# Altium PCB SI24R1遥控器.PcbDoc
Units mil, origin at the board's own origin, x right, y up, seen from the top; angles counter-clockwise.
Board outline 3937 x 3344.8 mil, 2 copper layers (Top Layer, Bottom Layer); 46 components, 39 nets, 207 pads, 28 vias.
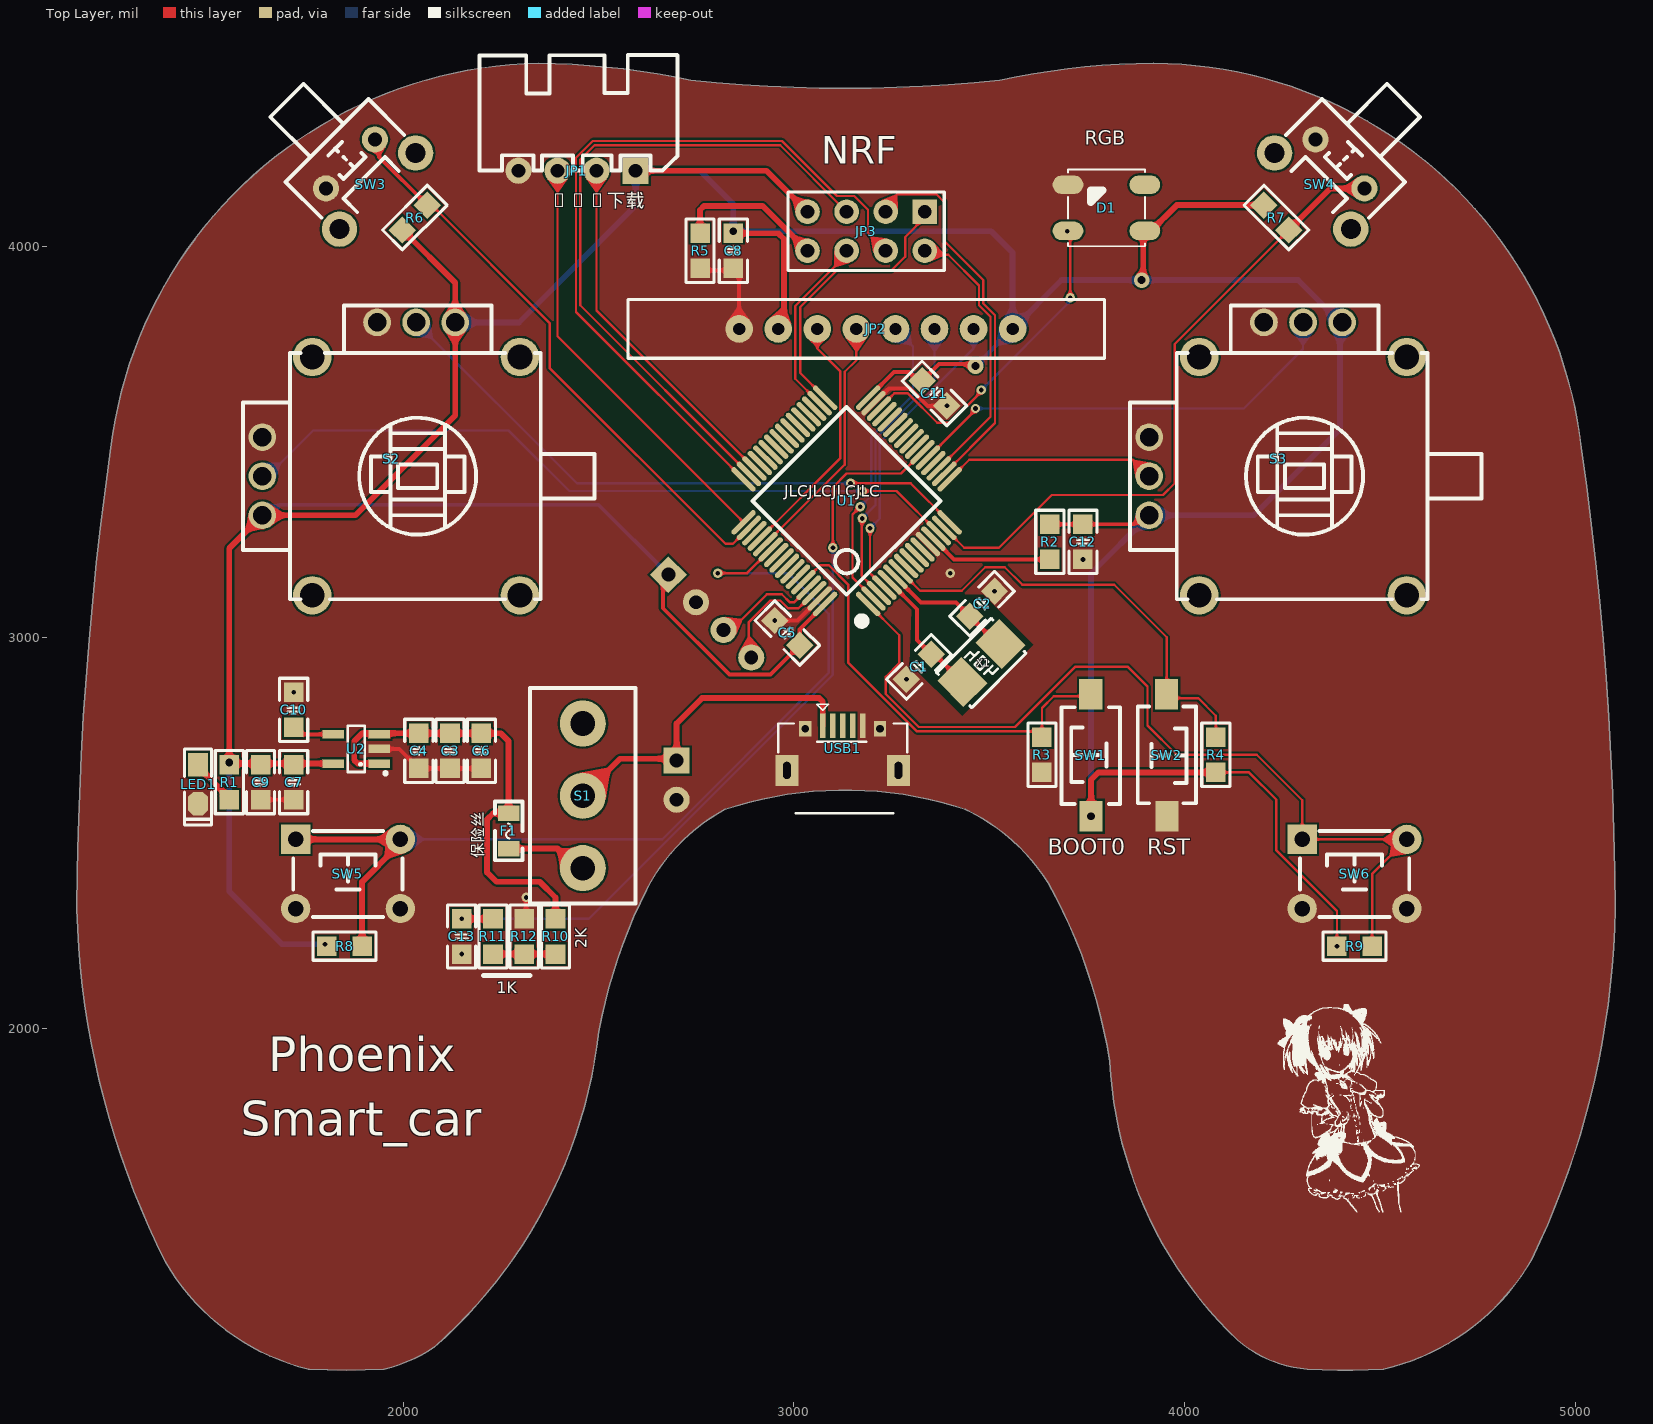
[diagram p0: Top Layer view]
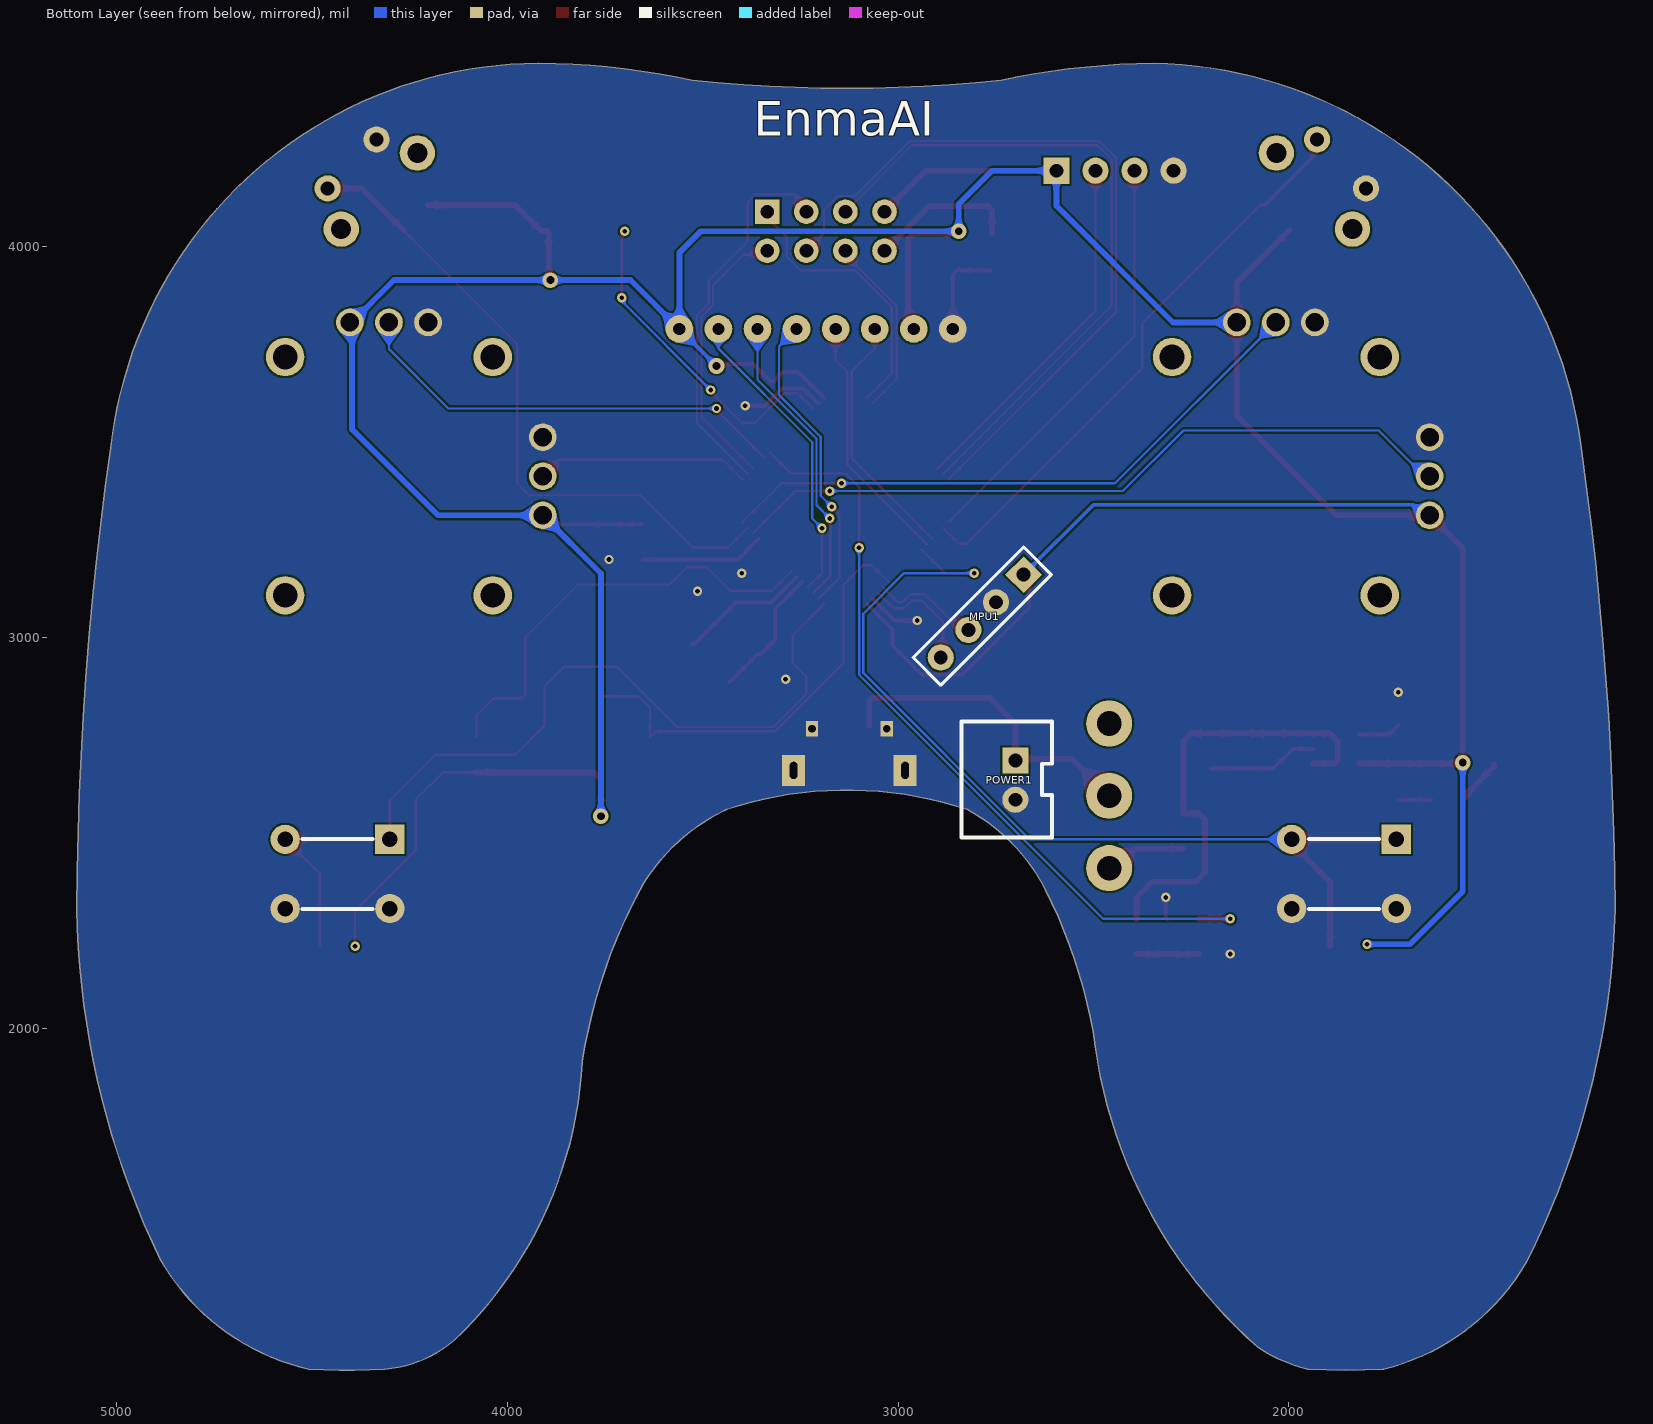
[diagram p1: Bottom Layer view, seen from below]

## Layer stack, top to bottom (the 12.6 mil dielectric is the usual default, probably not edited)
Top Solder: solder mask 0.4, Solder Resist, Dk 3.5
Top Layer: signal copper 1.4
Dielectric 1: dielectric 12.6, FR-4, Dk 4.8
Bottom Layer: signal copper 1.4
Bottom Solder: solder mask 0.4, Solder Resist, Dk 3.5

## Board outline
1391.35,1403.01 ccw(c1896.05,1692.9) 1758.26,1127.42 ccw(c1854.72,3093.56) 1951.17,1127.42 ccw(c1858.16,1512.49) 2080.33,1184.51 ccw(c1244.42,2133.09) 2489.78,1914.82 cw(c3809.86,1754.87) 2623.64,2355.76 cw(c3053.63,2134.86) 2824.42,2560.49 2822.89,2560.01 cw(c3131.51,1625.39) 3440.13,2560.01 3438.6,2560.49 cw(c3223.76,2104.73) 3651.2,2371.51 cw(c2447.28,1700.87) 3808.68,1914.82 ccw(c4866.07,1968.48) 4135.45,1202.22 ccw(c4338.85,1437.13) 4313.68,1127.42 ccw(c4411.21,3093.5) 4508.75,1127.42 ccw(c4376.69,1703.01) 4888.5,1408.39 ccw(c2976.27,2337.47) 5102,2304.49 5101.99,2304.49 ccw(c-3410.85,2274.06) 5015.39,3485.6 ccw(c3915.01,3362.63) 3920.9,4469.85 ccw(c3935.61,2507.77) 3527.2,4426.93 cw(c3130.23,8185.49) 2736.09,4426.63 ccw(c2324.92,2497.47) 2346.1,4469.85 ccw(c2365.85,3347.23) 1251.61,3485.59 1251.61,3485.6 ccw(c9946.59,2254.27) 1165,2304.5 1165,2304.49 ccw(c3290.29,2358.97)

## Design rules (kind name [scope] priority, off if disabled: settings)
Clearance [All] p1: gap=5 ignorepadtopadclearanceinfootprint=FALSE
Height [All] p1: minheight=0 maxheight=10000 prefheight=500
HoleSize [All] p1: absolutevalues=TRUE maxlimit=1000 minlimit=1 maxpercent=80.000 minpercent=20.000
HoleToHoleClearance [All] p1: gap=0 allowstackedmicrovias=TRUE
MinimumSolderMaskSliver [All] p1: minsoldermaskwidth=0
PlaneConnect [All] p1: planeconnectstyle=Direct reliefexpansion=20 reliefentries=4 reliefconductorwidth=10 reliefairgap=10
PolygonConnect [All] p1: connectstyle=Direct reliefconductorwidth=10 reliefentries=4 polygonreliefangle="90 Angle" airgapwidth=10
RoutingVias [All] p1: holewidth=12 width=24 viastyle="Through Hole" minholewidth=12 minwidth=24 maxholewidth=50 maxwidth=100
SilkToSilkClearance [All] p1: silktosilkclearance=0
SolderMaskExpansion [All] p1: expansion=4
Width [All] p1: maxlimit=100 minlimit=6 preferedwidth=6
24 further rules are at their usual default settings.

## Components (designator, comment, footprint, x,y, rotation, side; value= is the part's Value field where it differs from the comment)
C1 "18pF" "C 0805_M" 3320,2925 r45 top
C2 "18pF" "C 0805_M" 3481.82,3086.82 r225 top
C3 "100uF" "C 0805_M" 2120,2710 r90 top
C4 "100uF" "C 0805_M" 2040,2710 r90 top
C5 "0.1uF" "C 0805_M" 2983.18,3011.82 r315 top
C6 "22uF" "C 0805_M" 2200,2710 r90 top
C7 "22uF" "C 0805_M" 1720,2630 r90 top
C8 "10uF" "C 0805_M" 2845,3990 r90 top
C9 "10uF" "C 0805_M" 1635,2630 r90 top
C10 "0.1uF" "C 0805_M" 1720,2815 r270 top
C11 "0.1uF" "C 0805_M" 3360,3625 r135 top
C12 "0.1uF" "C 0805_M" 3740,3245 r90 top
C13 "0.1uF" "C 0805_M" 2150,2235 r90 top
D1 "P923D" RGB_LED_5050 3800,4100 r270 top
F1 "1A" "FU 0805" 2270,2505 r90 top
JP1 "HDR-1X4" XH2.54-WI-4P 2445,4195 r180 top
JP2 "HDR-1X8" IPS 2960,3785 r0 top
JP3 "Header 4X2" HDR2.54-LI-2x4P 3185,4040 r180 top
LED1 "蓝色" "LED 0805B" 1475,2625 r270 top
MPU1 "HDR-1X4" HDR2.54-LI-4P 2785,3055 r315 bottom
POWER1 "" XH2.54-LI-2P 2700,2635 r270 bottom
R1 "Res2" "R 0805_M" 1555,2630 r90 top
R2 "0" "R 0805_M" 3655,3245 r90 top
R3 "10K" "R 0805_M" 3635,2700 r270 top
R4 "10K" "R 0805_M" 4080,2700 r90 top
R5 "0" "R 0805_M" 2760,3990 r90 top
R6 "10K" "R 0805_M" 2030,4075 r45 top
R7 "10K" "R 0805_M" 4235,4075 r315 top
R8 "10K" "R 0805_M" 1850,2210 r0 top
R9 "10K" "R 0805_M" 4435,2210 r0 top
R10 "Res2" "R 0805_M" 2390,2235 r90 top
R11 "Res2" "R 0805_M" 2230,2235 r270 top
R12 "Res2" "R 0805_M" 2310,2235 r270 top
S1 "SS-12F23" SS-12D10 2460,2595.04 r90 top
S2 "摇杆" 3D161摇杆 2045,3440 r180 top
S3 "摇杆" 3D161摇杆 4315,3440 r180 top
SW1 "3x6x5" "TSW SMD-3*6*2.5" 3760,2700 r90 top
SW2 "3x6x5" "TSW SMD-3*6*2.5" 3955,2697.69 r270 top
SW3 "6x6x5" "TSW DIP-6*6*7_V" 1865,4212.37 r225 top
SW4 "6x6x5" "TSW DIP-6*6*7_V" 4397.64,4212.36 r135 top
SW5 "6x6x5" "TSW DIP-6*6*6" 1858.86,2395 r0 top
SW6 "6x6x5" "TSW DIP-6*6*6" 4435,2395 r0 top
U1 "MM32SPIN27PS" "LQFP64 10x10_M" 3135,3350 r45 top
U2 "MIC5219" SOT23-5M 1880,2715 r90 top
USB1 "USB-5P" USB-MICRO_A 3125,2660 r0 top
X1 "8MHz" "OSC 5032-2P" 3480,2935 r45 top

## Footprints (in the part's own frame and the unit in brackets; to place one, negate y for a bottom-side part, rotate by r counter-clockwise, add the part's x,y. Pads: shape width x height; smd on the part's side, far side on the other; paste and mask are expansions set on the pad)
3D161摇杆 [mm]
  round 1.8 hole 1.2: 1(10.298,3.226) 2(10.298,0.686) 3(10.298,-1.854) 4(2.838,-9.314) 5(0.298,-9.314) 6(-2.242,-9.314)
  round 2.5 hole 1.6 unplated: ""(-6.453,8.436) ""(-6.453,-7.063) ""(7.048,8.436) ""(7.048,-7.063)
  silkscreen extent -11.3,-10.41 11.56,8.69
"C 0805_M" [mil] "无极性贴片电容                                         淘宝ID:黄晶宝石"
  rect 50x50 smd: 1(-45,0) 2(45,0)
  silkscreen extent -81,-36 81,36, body extent -39,-24 39,24, height 20
"FU 0805" [mil] "贴片保险丝"
  rect 40x55 smd: 1(-45,0) 2(45,0)
  silkscreen extent -75,-35 75,35, body extent -39,-24 39,24, height 20
HDR2.54-LI-2x4P [mm] "双排排针，4x2脚 淘宝ID:黄晶宝石   店铺网址:https://shop463601444.taobao.com"
  rect 1.6x1.6 hole 0.9: 1(-3.81,-1.27)
  round 1.6 hole 0.9: 2(-3.81,1.27) 3(-1.27,-1.27) 4(-1.27,1.27) 5(1.27,-1.27) 6(1.27,1.27) 7(3.81,-1.27) 8(3.81,1.27)
  silkscreen extent -5.08,-2.54 5.08,2.54, body extent -5.08,-2.54 5.08,2.54, height 8.5
HDR2.54-LI-4P [mm] "排针，4脚"
  rect 1.7x1.7 hole 0.9: 1(-3.81,0)
  round 1.7 hole 0.9: 2(-1.27,0) 3(1.27,0) 4(3.81,0)
  silkscreen extent -5.08,-1.27 5.08,1.27, body extent -5.08,-1.27 5.08,1.27, height 8.5
IPS [mm]
  round 1.8 hole 0.8: 1(-2.54,0.127) 2(0,0.127) 3(2.54,0.127) 4(5.08,0.127) 5(7.62,0.127) 6(10.16,0.127) 7(12.7,0.127) 8(15.24,0.127)
  silkscreen extent -9.78,-1.78 21.21,2.05
"LED 0805B" [mil] "蓝色0805LED                                    淘宝ID:黄晶宝石"
  rect 60x50 smd: 1(-50,0)
  oct 60x50 smd: 2(50,0)
  silkscreen extent -90,-35 105,35, body extent -39,-25 39,25, height 32
"LQFP64 10x10_M" [mm] "64脚，体宽10x10mm，脚距0.5mm         淘宝ID:黄晶宝石"
  oval 0.35x2.1 smd: 1(-3.75,-5.727) 2(-3.25,-5.727) 3(-2.75,-5.727) 4(-2.25,-5.727) 5(-1.75,-5.727) 6(-1.25,-5.727) 7(-0.75,-5.727) 8(-0.25,-5.727) 9(0.25,-5.727) 10(0.75,-5.727) 11(1.25,-5.727) 12(1.75,-5.727) 13(2.25,-5.727) 14(2.75,-5.727) 15(3.25,-5.727) 16(3.75,-5.727) 33(3.75,5.727) 34(3.25,5.727) 35(2.75,5.727) 36(2.25,5.727) 37(1.75,5.727) 38(1.25,5.727) 39(0.75,5.727) 40(0.25,5.727) 41(-0.25,5.727) 42(-0.75,5.727) 43(-1.25,5.727) 44(-1.75,5.727) 45(-2.25,5.727) 46(-2.75,5.727) 47(-3.25,5.727) 48(-3.75,5.727)
  oval 2.1x0.35 smd: 17(5.727,-3.75) 18(5.727,-3.25) 19(5.727,-2.75) 20(5.727,-2.25) 21(5.727,-1.75) 22(5.727,-1.25) 23(5.727,-0.75) 24(5.727,-0.25) 25(5.727,0.25) 26(5.727,0.75) 27(5.727,1.25) 28(5.727,1.75) 29(5.727,2.25) 30(5.727,2.75) 31(5.727,3.25) 32(5.727,3.75) 49(-5.727,3.75) 50(-5.727,3.25) 51(-5.727,2.75) 52(-5.727,2.25) 53(-5.727,1.75) 54(-5.727,1.25) 55(-5.727,0.75) 56(-5.727,0.25) 57(-5.727,-0.25) 58(-5.727,-0.75) 59(-5.727,-1.25) 60(-5.727,-1.75) 61(-5.727,-2.25) 62(-5.727,-2.75) 63(-5.727,-3.25) 64(-5.727,-3.75)
  silkscreen extent -5.08,-6.47 4.32,4.32, body extent -6,-6 6,6, height 1.45
"OSC 5032-2P" [mm] "5mm*3.2mm*0.8mm(长*宽*高)                  淘宝ID:黄晶宝石"
  rect 2.2x2.4 smd: 1(-1.75,0) 2(1.75,0)
  silkscreen extent -2.5,-1.6 2.5,1.6, body extent -2.5,-1.6 2.5,1.6, height 0.86
"R 0805_M" [mil] "1/8W贴片电阻"
  rect 50x50 smd: 1(-45,0) 2(45,0)
  silkscreen extent -81,-36 81,36, body extent -39,-25 39,25, height 20
RGB_LED_5050 [mm]
  oval 1.2x2 smd: 1(-1.5,-2.5) 2(1.5,-2.5) 3(1.5,2.5) 4(-1.5,2.5)
  silkscreen extent -2.5,-2.5 2.5,2.5, body extent -2.5,-2.7 2.5,2.7, height 1.55
SOT23-5M [mm] "3x1.6x1.1mm(长宽高) 封装库来自淘宝卖家 ID：黄晶宝石"
  rect 0.55x1.4 smd: 1(-0.95,-1.5) 2(0,-1.5) 3(0.95,-1.5) 4(0.95,1.5) 5(-0.95,1.5)
  silkscreen extent -1.66,-1.98 1.5,0.56, body extent -1.5,-1.4 1.5,1.4, height 1.15
SS-12D10 [mm] "脚距3mm      淘宝ID:黄晶宝石"
  round 3 hole 1.6: 1(-4.7,0) 2(0,0) 3(4.7,0)
  silkscreen extent -7,-3.43 7,3.43, body extent -7,-3.1 7,3.1, height 9.65
"TSW DIP-6*6*6" [mm] "6*6*6mm"
  rect 1.9x1.9 hole 1: 1(-3.4,2.25)
  round 1.9 hole 1: 2(-3.4,-2.25) 3(3.4,-2.25) 4(3.4,2.25)
  silkscreen extent -3.56,-2.79 3.56,2.79, body extent -4.11,-3 4.11,3, height 5.95
"TSW DIP-6*6*7_V" [mm] "侧按轻触开关 6*6*7mm           淘宝ID:黄晶宝石"
  round 2.3 hole 1.3: 0(-3.5,2.5) 0(3.5,2.5)
  round 1.7 hole 0.9: 1(-2.25,0) 2(2.25,0)
  silkscreen extent -3.81,-5.84 3.81,2.54, body extent -4.18,-5.72 4.18,4.13, height 7.47
"TSW SMD-3*6*2.5" [mm] "3*6*2.5mm"
  rect 2x1.5 smd: 1(-3.996,-0.02) 2(3.937,0)
  silkscreen extent -3.21,-1.9 3.09,1.9, body extent -4,-1.88 4,1.62, height 2.59
USB-MICRO_A [mm] "micro型USB ，5.7*7.8*2.5mm"
  rect 0.35x1.6 smd: 1(-1.3,2.9) 2(-0.65,2.9) 3(0,2.9) 4(0.65,2.9) 5(1.3,2.9)
  rect 1.5x2 hole 0.5 slot 1.1 at 90 deg: 5(-3.625,0) 5(3.625,0)
  rect 0.8x1 hole 0.5: 5(-2.425,2.71) 5(2.425,2.71)
  silkscreen extent -4.19,-2.79 4.19,4.3, body extent -4,-2.71 4,2.89, height 2.8
XH2.54-LI-2P [mm] "接插件，2P  淘宝ID:黄晶宝石   店铺网址:https://shop463601444.taobao.com"
  rect 1.7x1.7 hole 0.9: 1(-1.27,0)
  round 1.7 hole 0.9: 2(1.27,0)
  silkscreen extent -3.81,-3.51 3.74,2.37, body extent -3.77,-3.3 3.77,2.4, height 7.05
XH2.54-WI-4P [mm] "接插件，4P"
  rect 1.7x1.7 hole 0.9: 1(-3.81,0)
  round 1.7 hole 0.9: 2(-1.27,0) 3(1.27,0) 4(3.81,0)
  silkscreen extent -6.53,-7.53 6.35,0, body extent -6.31,-7.35 6.31,0.35, height 5.73

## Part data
C1 C2 C3 C4 C5 C6 C7 C8 C9 C10 C11 C12 C13: library part C, "贴片电容"
F1: library part FU, "贴片保险丝"
JP1 MPU1: library part "Header 4", "4P接插件"
JP2: library part "Header 8", "8P接插件"
JP3: "4*2P接插件"
LED1: library part LED-SMD, "贴片LED"
POWER1: library part T槽
R1 R10 R11 R12: "Resistor"
R2 R3 R4 R5 R6 R7 R8 R9: library part RES
S1: library part SSW-1P, "1路波动开关"
SW1 SW2: library part "TSW 3x6", "3x6轻触开关"
SW3 SW4: library part "TSW DIP-6x6_V", "侧按直插6x6轻触开关"
SW5 SW6: library part "TSW DIP-6x6", "直插6x6轻触开关"
USB1: "微型USB母座"
X1: library part XTAL-2P, "2脚无源脚晶振"

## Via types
v1: diameter 24, hole 12, Top Layer to Bottom Layer, tented both sides, 23 vias
v2: diameter 40, hole 20, Top Layer to Bottom Layer, tented both sides, 5 vias

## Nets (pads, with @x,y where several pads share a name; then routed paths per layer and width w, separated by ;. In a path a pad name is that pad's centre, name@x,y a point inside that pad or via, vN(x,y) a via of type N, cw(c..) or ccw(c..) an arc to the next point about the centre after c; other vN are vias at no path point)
ADC_IN1: S2.2 U1.14 | length 1888.8
  Top Layer w6: v1(3175,3375) 3263.11,3375 U1.14
  Bottom Layer w6: S2.2 1652.99,3412.99 1770,3530 2270,3530 2425,3375 v1(3175,3375)
ADC_IN2: S2.5 U1.16 | length 1577.5
  Top Layer w6: v1(3145,3395) 3298.79,3395 U1.16
  Bottom Layer w6: S2.5 2444.97,3395 v1(3145,3395)
ADC_IN3: S3.2 U1.17 | length 548.8
  Top Layer w6: U1.17 3448.79,3455 3867.56,3455 S3.2
ADC_IN4: S3.5 U1.21 | length 1149.4
  Top Layer w6: U1.21 3465,3582.56 v1(3465,3586.28) v1@3465,3590
  Bottom Layer w6: v1(3465,3586.28) 4151.28,3586.28 4303.27,3738.27 S3.5
BOOT0: R3.1 SW1.2 U1.60 | length 1142.5
  Top Layer w6: U1.60 3067.44,3185 3090,3185 3139,3136 3139,2936 3315,2760 3620,2760 R3.1 3635,2820 3665,2850 3755,2850 SW1.2
GND: C1.1 C2.1 C3.1 C4.1 C5.1 C6.1 C7.1 C8.1 C9.1 C10.1 C11.1 C12.1 C13.1 D1.1 JP1.4 JP2.1 LED1.2 MPU1.2 POWER1.2 R3.2 R5.1 R12.1 S2.3 S2.4 S3.3 S3.4 SW2.2 SW3.2 SW4.2 SW5.2 SW5.3 SW6.2 SW6.3 U1.12 U1.31 U1.63 U2.2 USB1.5 | length 1027.3
  Top Layer w10: C9.1 C7.1 ; U2.2 1990,2715 C4.1 C6.1 ; R12.1 2315,2285 v1(2315,2335) ; R5.1@2765,3940 2840,3940 C8.1 2860,3930 JP2.1 ; v1(2951.36,3043.64) 3009.59,3043.64 U1.63 ; U1.31 3204.98,3599.91 3243.07,3638 3297.5,3638 3342.32,3593.18 v1(3391.82,3593.18)
  other v1: 2150,2190 1720,2860 3288.18,2893.18 3513.64,3118.64 3400,3165 3740,3200
KEY1: R6.2 SW3.1 U1.50 | length 1490.5
  Top Layer w6: R6.2 2073.18,4106.82 2375,3805 2375,3690 2825,3240 2844.05,3240 U1.50
  Top Layer w10: SW3.1 1938.53,4264.12 1938.53,4230.11 R6.2
KEY2: R7.2 SW4.1 U1.15 | length 1686.2
  Top Layer w6: U1.15 3435.95,3230 3525,3230 3660,3365 3945,3365 3975,3395 3975,3751.36 R7.2
  Top Layer w15: R7.2 4373.36,4149.73 SW4.1
KEY3: R8.2 SW5.1 SW5.4 U1.54 | length 2493.8
  Top Layer w6: v1(2805,3165) 2880.4,3165 U1.54
  Top Layer w15: SW5.1 SW5.4 1981.27,2472.14 1981.27,2461.27 1895,2375 R8.2
  Bottom Layer w6: SW5.4 2663.03,2483.58 3089,2909.56 3089,3061 2985,3165 v1(2805,3165)
KEY4: R9.2 SW6.1 SW6.4 U1.1 | length 2321.5
  Top Layer w6: U1.1 3270,3006.21 3270,2935 3235,2900 3235,2855.56 3319.56,2771 3566,2771 3720,2925 3855,2925 3905,2875 3905,2775 3980,2700 4185,2700 4301.14,2583.86 SW6.1 SW6.4 4480,2394.72 R9.2
M3V3: C5.2 C7.2 C8.2 C9.2 C11.2 C12.2 D1.3 JP1.1 JP2.2 JP2.8 JP3.7 MPU1.1 R1.2 R2.2 R4.1 R6.1 R7.1 R8.1 R9.1 S2.1 S2.6 S3.1 S3.6 SW1.1 U1.32 U1.64 U2.5 | length 12182.1
  Top Layer w6: R4.1 4165,2655 4235,2585 4235,2455 4390,2300 v1(4390,2210)
  Top Layer w10: MPU1.1 2665,3147.13 2665,3075 2835,2905 2940,2905 C5.2 3015,3021.21 U1.64 ; U1.32 3256.21,3680 3295,3680 3318.18,3656.82 C11.2 3371.36,3700 v2@3465,3700 ; R2.2 C12.2 3870.11,3290 3893.1,3312.99 S3.1
  Top Layer w15: U2.5 1557.6,2677.6 R1.2 1555,3228.42 S2.1 1877.99,3312.99 2133.27,3568.27 S2.6 2133.27,3908.09 R6.1 ; JP1.1 2930,4195 JP3.7 ; C8.2 2960,4035 2975,4020 2975,3805 JP2.2 ; v2(3760.79,2542.69) 3760.79,2635.79 3780,2655 R4.1 ; v2(3890,3915) 3894.21,3919.21 3894.21,4036.73 D1.3 3914.17,4040.94 3980.05,4106.82 R7.1
  Bottom Layer w10: S2.1 1656.04,3312.99 1683.05,3340 2500,3340 MPU1.1 ; v2(3465,3695) JP2.8
  Bottom Layer w15: v2(1555,2680) 1555,2350 1690,2215 v1(1800,2215) ; S2.6 2296.69,3806.69 2595,4105 JP1.1 2760,4195 2845,4110 v2(2845,4040) 3505,4040 3560,3985 JP2.8 3685,3915 v2(3890,3915) 4290.25,3915 4398.56,3806.69 S3.6 4397.5,3800.92 4397.5,3532.5 4177.99,3312.99 S3.1 3760.79,3164.21 v2(3760.79,2542.69)
NetC10_2: C10.2 U2.4 | length 110.3
  Top Layer w10: C10.2@1720,2775 1742.6,2752.4 U2.4
NetF1_1: F1.1 S1.1 | length 210.7
  Top Layer w15: F1.1 2394.66,2460 2444.66,2410 S1.1
NetJP3_8: JP3.8 R5.2 | length 386.3
  Top Layer w15: R5.2 2760,4094.14 2770.86,4105 2920,4105 JP3.8
NetLED1_1: LED1.1 R1.1 | length 123.1
  Top Layer w15: LED1.1 1475,2670 1537.5,2607.5 1537.5,2602.5 R1.1
NetR2_1: R2.1 U1.13 | length 320
  Top Layer w10: U1.13 3410.27,3200 R2.1
NetR10_1: R10.1 R11.2 R12.2 | length 160
  Top Layer w15: R11.2 R10.1
NF_CE: JP3.6 U1.34 | length 474.7
  Top Layer w6: U1.34 3003.43,3662.52 3003.43,3848.43 JP3.6@3145,3990
NF_CS: JP3.5 U1.47 | length 1750.3
  Top Layer w6: U1.47 2453.54,3850.51 2453.54,4223.54 2490,4260 2965,4260 JP3.5
NF_IRQ: JP3.1 U1.33 | length 716
  Top Layer w6: U1.33 3016.57,3677.22 3016.57,3846.01 3110.56,3940 3250,3940 3285,3975 3285,4025 3335,4075 JP3.1
NF_SCL: JP3.4 U1.48 | length 1962.4
  Top Layer w6: U1.48 2442.54,3833.67 2442.54,4228.09 2485.44,4271 2969.56,4271 3110.28,4130.28 3154.72,4130.28 3190,4095 3190,4035 JP3.4
NF_SDI: JP3.3 U1.18 | length 1006.9
  Top Layer w6: JP3.3@3240.5,4074.5 3240.5,4084.5 JP3.3 3235,4105 3265,4135 3364.31,4135 3385,4114.31 3385,4015 3485,3915 3485,3855 3515,3825 3515,3549.05 U1.18
NF_SDO: JP3.2 U1.19 | length 711
  Top Layer w6: JP3.2 3345,3980 3395,3980 3474,3901 3474,3850.44 3503.43,3821.01 3503.43,3565.32 U1.19
nRST: R4.2 SW2.1 U1.7 | length 1149.7
  Top Layer w6: U1.7 3323.24,3120 3430,3120 3490,3180 3540,3180 3585,3135 3820,3135 3954.21,3000.79 SW2.1 3964.21,2845 4035,2845 4080,2800 R4.2
OLED_CS: JP2.7 U1.4 | length 787.1
  Top Layer w6: v1(3195,3280) 3195,3164.73 U1.4
  Bottom Layer w6: v1(3195,3280) 3220,3305 3220,3500 3460,3740 JP2.7
OLED_DC: JP2.6 U1.3 | length 771.2
  Top Layer w6: v1(3175,3305) 3174,3304 3174,3157.89 U1.3
  Bottom Layer w6: v1(3175,3305) 3209,3339 3209,3509 3360,3660 JP2.6
OLED_RES: JP2.5 U1.2 | length 795.1
  Top Layer w6: v1(3170,3335) 3150,3315 3150,3154.05 U1.2
  Bottom Layer w6: v1(3170,3335) 3198,3363 3198,3513.56 3305,3620.56 3305,3745 JP2.5
OLED_SCL: JP2.3 U1.52 | length 646.8
  Top Layer w6: U1.52 3119.21,3459.49 3119.21,3680.79 3060,3740 JP2.3
OLED_SDA: JP2.4 U1.53 | length 647.3
  Top Layer w6: U1.53 3130.21,3442.65 3130.21,3680.21 3160,3710 JP2.4
OSC_IN: C1.2 U1.5 X1.1 | length 337.7
  Top Layer w10: U1.5 3315,3072.56 3315,2993.64 C1.2 3360.74,2956.82 X1.1
OSC_OUT: C2.2 U1.6 X1.2 | length 340.3
  Top Layer w10: U1.6 3325.4,3090 3415,3090 C2.2 3521.28,2983.72 X1.2
POWER_IN: C13.2 R11.1 U1.22 | length 2035.2
  Top Layer w6: v1(3100,3230) 3100,3385 3135,3420 3274.6,3420 U1.22
  Top Layer w15: v1(2150,2280) R11.1
  Bottom Layer w6: v1(2150,2280) 2475,2280 3100,2905 v1(3100,3230)
RGBLED: D1.2 U1.30 | length 852.5
  Top Layer w6: U1.30 3256.89,3625 3292.12,3625 3367.29,3549.82 3399.82,3549.82 3480,3630 v1(3480,3633.75) ; v1(3700,4040) 3707.5,4032.5 v1(3707.5,3870)
  Bottom Layer w6: v1(3480,3633.75) 3707.5,3861.25 v1(3707.5,3870) v1@3710,3870
SCL: MPU1.3 U1.61 | length 280.1
  Top Layer w6: MPU1.3 2839.64,3019.64 2931,3111 2969,3111 2990,3090 3000.27,3090 U1.61
SDA: MPU1.4 U1.62 | length 307.9
  Top Layer w6: MPU1.4 2885,2955 2885,3040 2940,3095 2965,3095 2985,3075 3011.94,3075 3050.95,3114.01 U1.62
SWCLK: JP1.3 U1.49 | length 1097.3
  Top Layer w6: JP1.3 2395,3771.13 U1.49
SWDIO: JP1.2 U1.46 | length 929.5
  Top Layer w6: JP1.2 2495,3836.89 U1.46
VCC: POWER1.1 S1.2 USB1.1 | length 842.8
  Top Layer w15: S1.2 2554.96,2690 2695,2690 POWER1.1 2700,2780 2765,2845 3065.03,2845 3073.82,2836.21 USB1.1
VCC_IN: C3.2 C4.2 C6.2 F1.2 R10.2 U2.1 U2.3 | length 1168.9
  Top Layer w15: U2.1 1883.79,2677.6 1875,2686.39 1875,2735 1895,2755 1936.46,2755 U2.3 1941.65,2755 C4.2 C3.2 C6.2 2250,2755 2270,2735 F1.2 2230,2550 2215,2535 2215,2398.79 2238.79,2375 2350,2375 2390,2335 R10.2
pads on no net: D1.4 S1.3 S2. S3. SW3.0 SW4.0 U1.8 U1.9 U1.10 U1.11 U1.20 U1.23 U1.24 U1.25 U1.26 U1.27 U1.28 U1.29 U1.35 U1.36 U1.37 U1.38 U1.39 U1.40 U1.41 U1.42 U1.43 U1.44 U1.45 U1.51 U1.55 U1.56 U1.57 U1.58 U1.59 USB1.2 USB1.3 USB1.4

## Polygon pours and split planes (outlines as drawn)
GND on Top Layer (solid, remove dead copper, pour order 4): 1391.35,1403.01 ccw(c1896.05,1692.9) 1758.26,1127.42 ccw(c1854.72,3093.56) 1951.17,1127.42 ccw(c1858.16,1512.49) 2080.33,1184.51 ccw(c1244.42,2133.09) 2489.78,1914.82 cw(c3809.86,1754.87) 2623.64,2355.76 cw(c3053.63,2134.86) 2824.42,2560.49 2822.89,2560.01 cw(c3131.51,1625.39) 3440.13,2560.01 3438.6,2560.49 cw(c3223.76,2104.73) 3651.2,2371.51 cw(c2447.28,1700.87) 3808.68,1914.82 ccw(c4866.07,1968.48) 4135.45,1202.22 ccw(c4338.85,1437.13) 4313.68,1127.42 ccw(c4411.21,3093.5) 4508.75,1127.42 ccw(c4376.69,1703.01) 4888.5,1408.39 ccw(c2976.27,2337.47) 5102,2304.49 5101.99,2304.49 ccw(c-3410.85,2274.06) 5015.39,3485.6 ccw(c3915.01,3362.63) 3920.9,4469.85 ccw(c3935.61,2507.77) 3527.2,4426.93 cw(c3130.23,8185.49) 2736.09,4426.63 ccw(c2324.92,2497.47) 2346.1,4469.85 ccw(c2365.85,3347.23) 1251.61,3485.59 1251.61,3485.6 ccw(c9946.59,2254.27) 1165,2304.5 1165,2304.49 ccw(c3290.29,2358.97)
GND on Bottom Layer (solid, remove dead copper, pour order 6): 1391.35,1403.01 ccw(c1896.05,1692.9) 1758.26,1127.42 ccw(c1854.72,3093.56) 1951.17,1127.42 ccw(c1858.16,1512.49) 2080.33,1184.51 ccw(c1244.42,2133.09) 2489.78,1914.82 cw(c3809.86,1754.87) 2623.64,2355.76 cw(c3053.63,2134.86) 2824.42,2560.49 2822.89,2560.01 cw(c3131.51,1625.39) 3440.13,2560.01 3438.6,2560.49 cw(c3223.76,2104.73) 3651.2,2371.51 cw(c2447.28,1700.87) 3808.68,1914.82 ccw(c4866.07,1968.48) 4135.45,1202.22 ccw(c4338.85,1437.13) 4313.68,1127.42 ccw(c4411.21,3093.5) 4508.75,1127.42 ccw(c4376.69,1703.01) 4888.5,1408.39 ccw(c2976.27,2337.47) 5102,2304.49 5101.99,2304.49 ccw(c-3410.85,2274.06) 5015.39,3485.6 ccw(c3915.01,3362.63) 3920.9,4469.85 ccw(c3935.61,2507.77) 3527.2,4426.93 cw(c3130.23,8185.49) 2736.09,4426.63 ccw(c2324.92,2497.47) 2346.1,4469.85 ccw(c2365.85,3347.23) 1251.61,3485.59 1251.61,3485.6 ccw(c9946.59,2254.27) 1165,2304.5 1165,2304.49 ccw(c3290.29,2358.97)

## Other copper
Top Layer:
  pour cut-out: 3296.81,2933.19 3430.42,2799.58 3612.92,2982.08 3485,3110 3303.31,3110

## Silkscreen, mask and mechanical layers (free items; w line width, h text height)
Top Overlay:
  drawing of 5340 lines, arcs and shapes, not listed
  text "RGB" at 3745,4250 h60
  text "NRF" at 3070,4190 h120
  text "SWD下载" at 2375,4090 h60
  text "JLCJLCJLCJLC" at 2975,3350 h50
  text "保险丝" at 2215,2435 h50 r90
  text "BOOT0" at 3650,2430 h70
  text "RST" at 3905,2430 h70
  text "2K" at 2480,2205 h50 r90
  text "1K" at 2240,2080 h50
  text "Phoenix" at 1655,1860 h150
  text "Smart_car" at 1585,1695 h150
Bottom Overlay:
  text "EnmaAI" at 3370,4255 h150
Mechanical 1:
  lines w10: 2822.89,2560.01 cw(c3131.51,1625.39) 3440.13,2560.01 ; 2824.42,2560.49 ccw(c3053.63,2134.86) 2623.64,2355.77 ccw(c3809.86,1754.87) 2489.78,1914.82 cw(c1244.42,2133.09) 2080.33,1184.51 cw(c1858.16,1512.49) 1951.17,1127.42 cw(c1854.72,3093.56) 1758.26,1127.42 cw(c1896.05,1692.9) 1391.35,1403.01 cw(c3290.29,2358.97) 1165,2304.49 cw(c9946.59,2254.27) 1251.61,3485.6 cw(c2365.85,3347.23) 2346.1,4469.85 cw(c2324.92,2497.47) 2736.09,4426.63 ccw(c3130.23,8185.49) 3527.2,4426.93 cw(c3935.61,2507.77) 3920.9,4469.85 cw(c3915.01,3362.63) 5015.39,3485.6 cw(c-3410.85,2274.06) 5101.99,2304.49 cw(c2976.27,2337.47) 4888.5,1408.39 cw(c4376.69,1703.01) 4508.75,1127.42 cw(c4411.21,3093.5) 4313.68,1127.42 cw(c4338.85,1437.13) 4135.45,1202.22 cw(c4866.07,1968.48) 3808.68,1914.82 ccw(c2447.28,1700.87) 3651.2,2371.51 ccw(c3223.76,2104.73) 3438.6,2560.49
